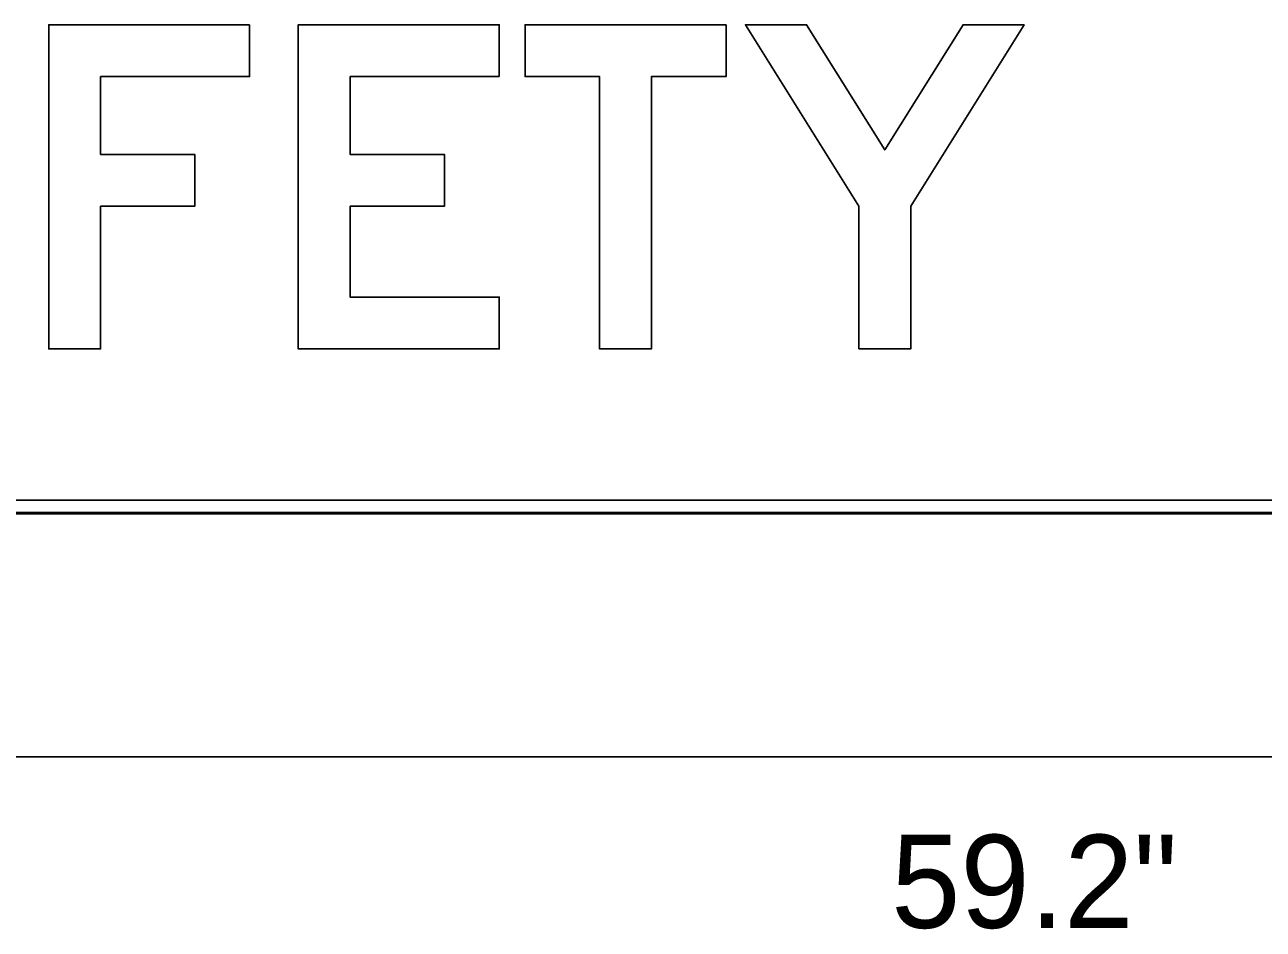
# Model space of a CAD drawing. Extents: x 0 to 770, y 0 to 495.
# Drawn here: x 245.44 to 292, y 411.05 to 445.04 of the extents above; entities that cross this region are included whole.
import ezdxf

# ---------------------------------------------------------------- set-up
doc = ezdxf.new("R2010")
doc.units = 0
for name, color, linetype in [('GSBWFill', 7, 'Continuous'), ('GSColorFill', 7, 'Continuous'), ('GSDims', 7, 'Continuous'), ('GSOutline', 7, 'Continuous'), ('TextStructures', 7, 'Continuous')]:
    doc.layers.add(name, color=color, linetype=linetype)

msp = doc.modelspace()

# ---------------------------------------------------------------- linework, layer by layer
at = {"layer": 'GSBWFill'}
for p, q in [((349.988, 427.171), (220.057, 427.171)), ((220.052, 426.664), (349.988, 426.664)), ((220.057, 426.664), (349.988, 426.664))]:
    msp.add_line(p, q, dxfattribs=at)
for points in [[(253.896, 445.037), (253.896, 443.088), (248.293, 443.088), (248.293, 440.165), (251.835, 440.165), (251.835, 438.216), (248.293, 438.216), (248.293, 432.856), (246.344, 432.856), (246.344, 445.037)], [(263.276, 443.088), (257.673, 443.088), (257.673, 440.165), (261.215, 440.165), (261.215, 438.216), (257.673, 438.216), (257.673, 434.805), (263.276, 434.805), (263.276, 432.856), (255.723, 432.856), (255.723, 445.037), (263.276, 445.037)], [(271.803, 445.037), (271.803, 443.088), (269.001, 443.088), (269.001, 432.856), (267.052, 432.856), (267.052, 443.088), (264.251, 443.088), (264.251, 445.037)], [(276.797, 432.856), (278.746, 432.856), (278.746, 438.216), (283.01, 445.037), (280.712, 445.037), (277.772, 440.334), (274.832, 445.037), (272.534, 445.037), (276.797, 438.216)]]:
    msp.add_lwpolyline(points, close=True, dxfattribs=at)
at = {"layer": 'GSColorFill'}
for p, q in [((349.988, 427.171), (220.057, 427.171)), ((220.052, 426.664), (349.988, 426.664)), ((349.988, 426.714), (220.053, 426.714)), ((220.053, 426.664), (349.988, 426.664)), ((220.057, 426.664), (349.988, 426.664))]:
    msp.add_line(p, q, dxfattribs=at)
for points in [[(253.896, 445.037), (253.896, 443.088), (248.293, 443.088), (248.293, 440.165), (251.835, 440.165), (251.835, 438.216), (248.293, 438.216), (248.293, 432.856), (246.344, 432.856), (246.344, 445.037)], [(263.276, 443.088), (257.673, 443.088), (257.673, 440.165), (261.215, 440.165), (261.215, 438.216), (257.673, 438.216), (257.673, 434.805), (263.276, 434.805), (263.276, 432.856), (255.723, 432.856), (255.723, 445.037), (263.276, 445.037)], [(271.803, 445.037), (271.803, 443.088), (269.001, 443.088), (269.001, 432.856), (267.052, 432.856), (267.052, 443.088), (264.251, 443.088), (264.251, 445.037)], [(276.797, 432.856), (278.746, 432.856), (278.746, 438.216), (283.01, 445.037), (280.712, 445.037), (277.772, 440.334), (274.832, 445.037), (272.534, 445.037), (276.797, 438.216)]]:
    msp.add_lwpolyline(points, close=True, dxfattribs=at)
at = {"layer": 'GSDims'}
msp.add_line((224.904, 417.527), (345.136, 417.527), dxfattribs=at)
at = {"layer": 'GSOutline'}
for p, q in [((220.052, 427.171), (349.988, 427.171)), ((220.052, 426.664), (349.988, 426.664)), ((220.052, 426.664), (349.988, 426.664))]:
    msp.add_line(p, q, dxfattribs=at)
for points in [[(253.896, 445.037), (253.896, 443.088), (248.293, 443.088), (248.293, 440.165), (251.835, 440.165), (251.835, 438.216), (248.293, 438.216), (248.293, 432.856), (246.344, 432.856), (246.344, 445.037)], [(263.276, 443.088), (257.673, 443.088), (257.673, 440.165), (261.215, 440.165), (261.215, 438.216), (257.673, 438.216), (257.673, 434.805), (263.276, 434.805), (263.276, 432.856), (255.723, 432.856), (255.723, 445.037), (263.276, 445.037)], [(271.803, 445.037), (271.803, 443.088), (269.001, 443.088), (269.001, 432.856), (267.052, 432.856), (267.052, 443.088), (264.251, 443.088), (264.251, 445.037)], [(276.797, 432.856), (278.746, 432.856), (278.746, 438.216), (283.01, 445.037), (280.712, 445.037), (277.772, 440.334), (274.832, 445.037), (272.534, 445.037), (276.797, 438.216)]]:
    msp.add_lwpolyline(points, close=True, dxfattribs=at)

# ---------------------------------------------------------------- texts
at = {"layer": 'TextStructures'}
msp.add_text('59.2"', height=3.5, dxfattribs=at).set_placement((278.01, 411.097))

doc.saveas('drawing.dxf')
